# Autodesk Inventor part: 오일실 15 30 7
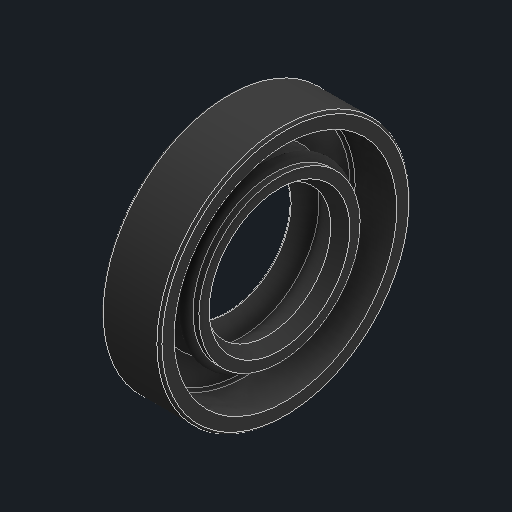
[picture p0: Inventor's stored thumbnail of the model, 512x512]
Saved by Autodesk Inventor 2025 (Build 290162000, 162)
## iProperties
Created: 2025-08
Part Number: 오일실 15 30 7
Material: 고무
Description: 오일-실
Document SubType Name: Modeling
Designer: infra023
Density: 0.93 g/cm^3
Appearance: 기본값
Author: jhkim
Sending System: Autodesk Inventor 2026
Preprocessor: ST-DEVELOPER v20.1
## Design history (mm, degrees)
feature "Solid1"
node "솔리드1"
